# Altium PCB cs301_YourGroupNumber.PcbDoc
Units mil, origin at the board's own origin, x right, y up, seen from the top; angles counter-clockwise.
Board outline 10825 x 6635 mil, 2 copper layers (Top Layer, Bottom Layer); 13 components, 95 nets, 86 pads, 0 vias.
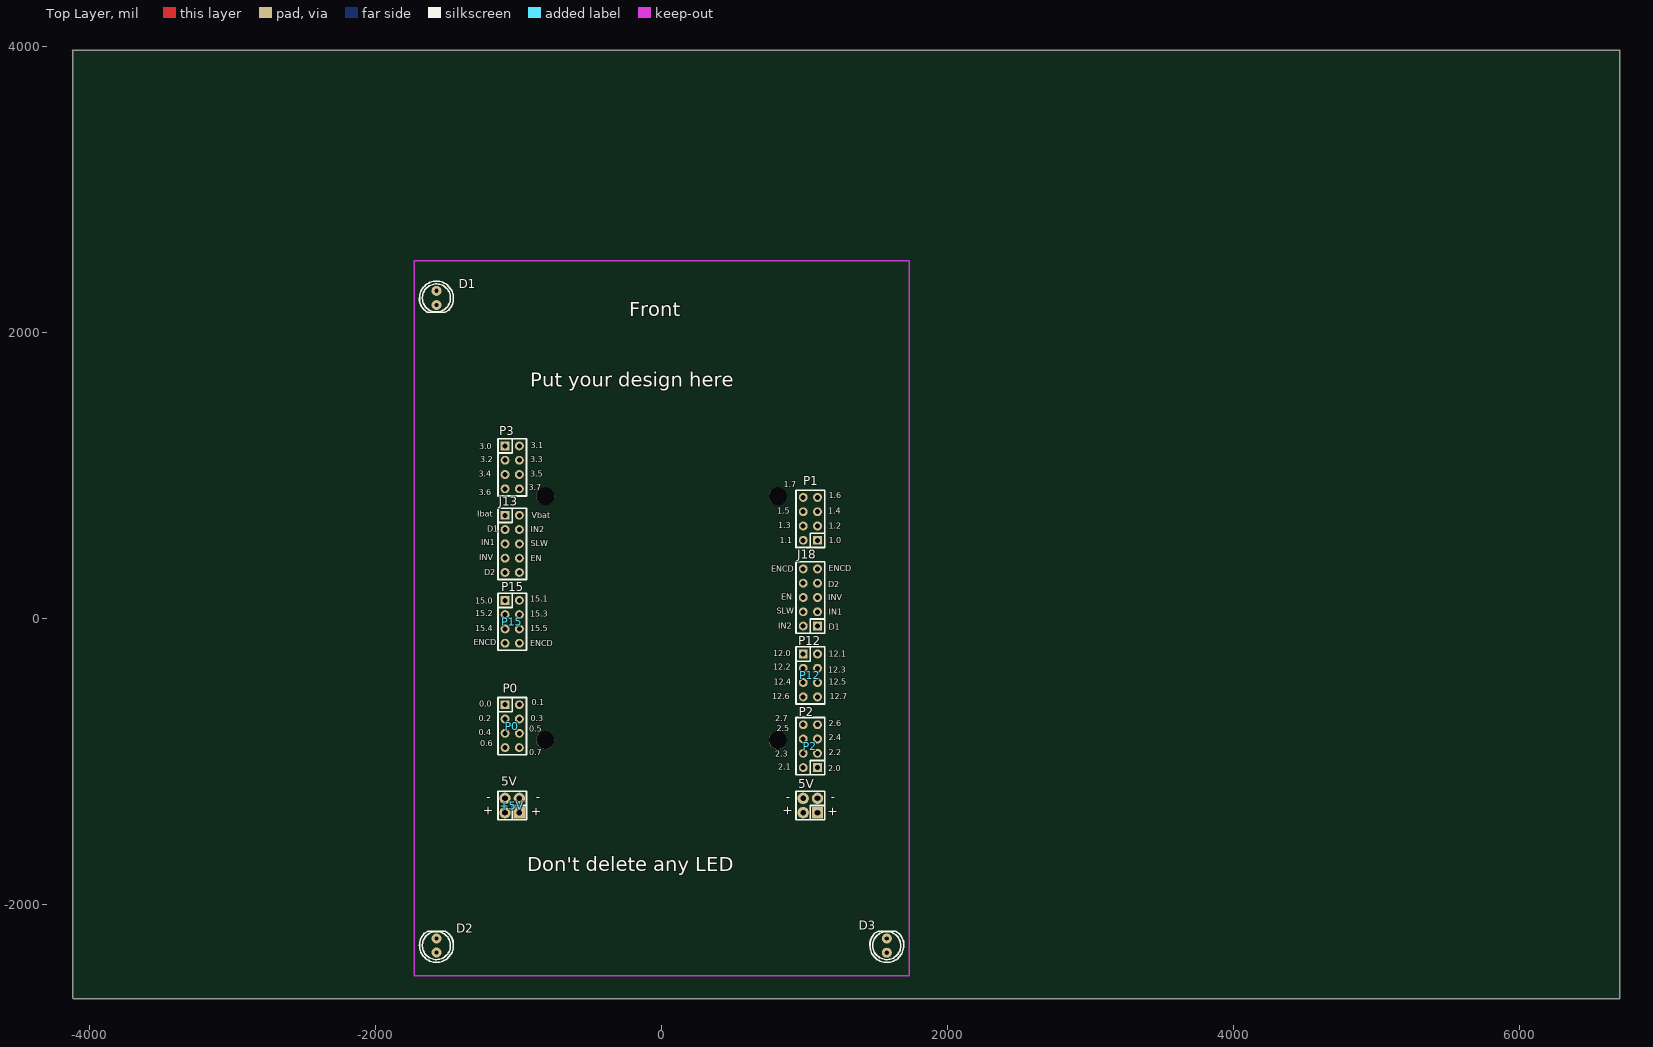
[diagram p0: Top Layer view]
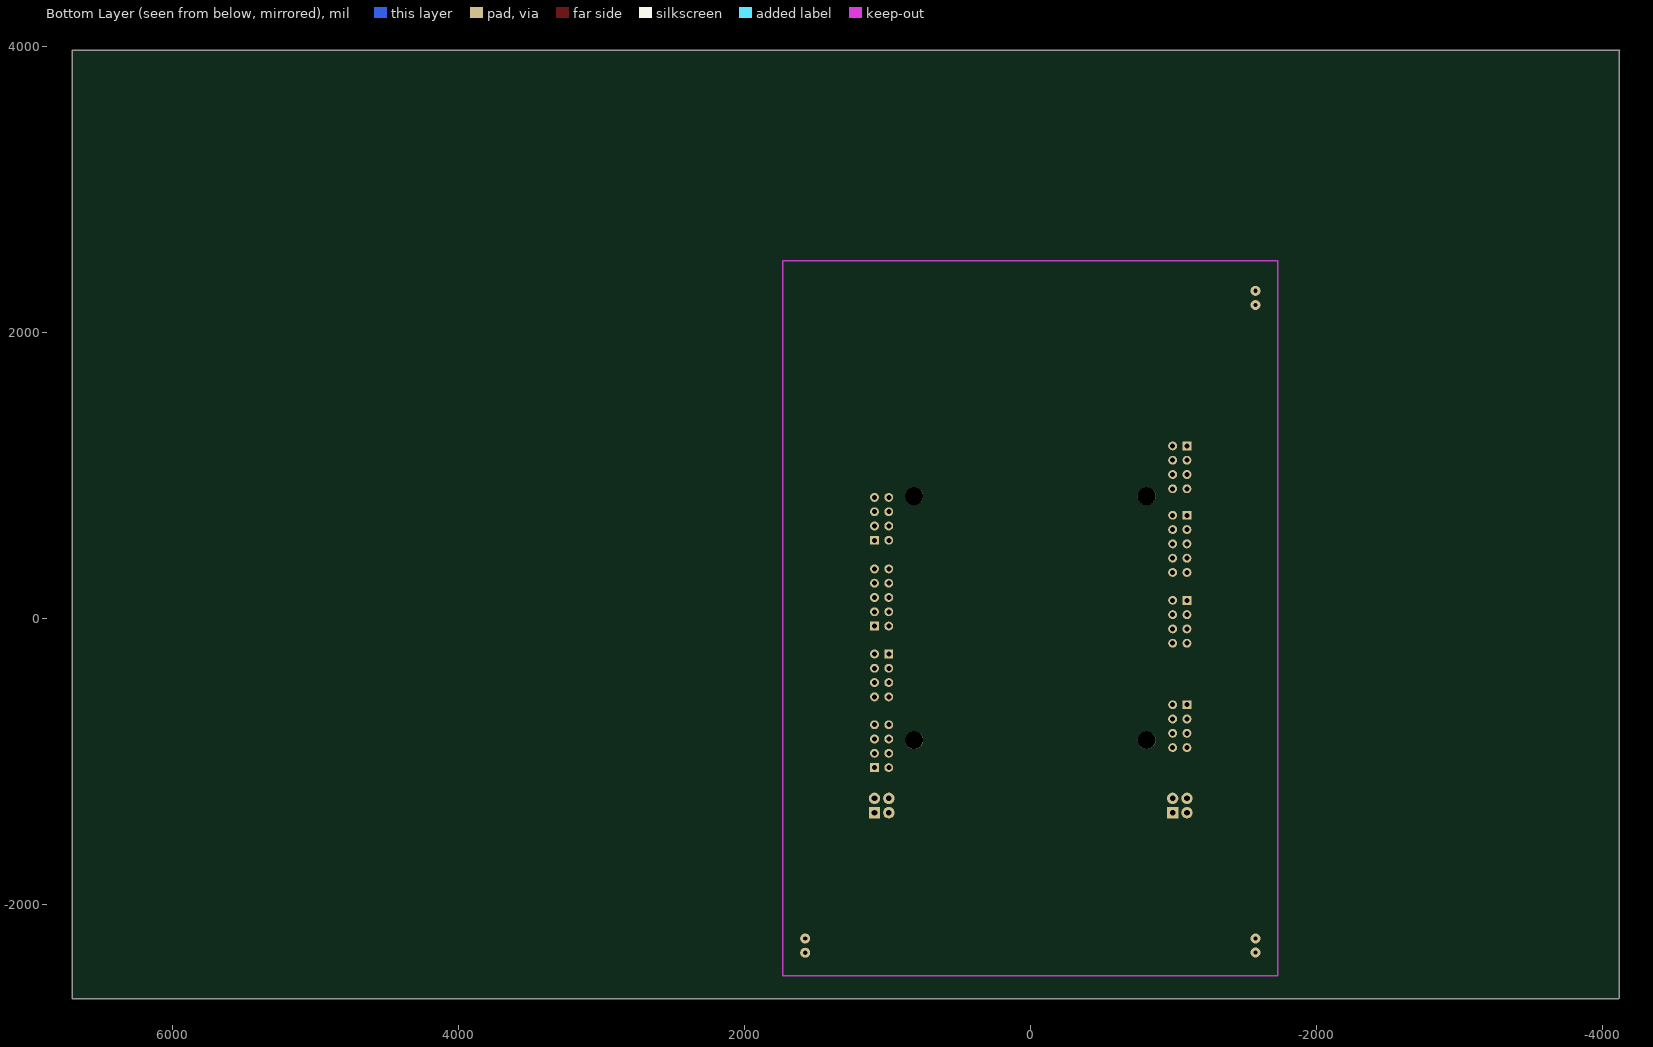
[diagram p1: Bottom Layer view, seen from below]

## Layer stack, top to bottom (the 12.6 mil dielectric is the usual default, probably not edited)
Top Solder: solder mask 0.4, Solder Resist, Dk 3.5
Top Layer: signal copper 1.4
Dielectric1: dielectric 12.6, FR-4, Dk 4.8
Bottom Layer: signal copper 1.4
Bottom Solder: solder mask 0.4, Solder Resist, Dk 3.5

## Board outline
-4118.11,-2656.69 -4113.11,-2661.69 6701.89,-2661.69 6701.89,3973.31 -4123.11,3973.31 -4118.11,3968.31 -4118.11,-2656.69

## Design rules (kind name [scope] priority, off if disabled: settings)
Clearance [All] p1: gap=10
PolygonConnect [All] p1: connectstyle=Relief reliefconductorwidth=20 reliefentries=4 polygonreliefangle="90 Angle" airgapwidth=10
RoutingVias [All] p1: holewidth=28 width=50 viastyle="Through Hole" minholewidth=28 minwidth=50 maxholewidth=28 maxwidth=50
SilkToSolderMaskClearance SilkscreenOverComponentPads [IsPad] p1: minsilkscreentomaskgap=10 clearancetoexposedcopper=TRUE
SolderMaskExpansion [All] p1: expansion=4
UnpouredPolygon [All] p1: allowunpoured=FALSE
Width [All] p1: maxlimit=30 minlimit=10 preferedwidth=10 minimp=50.000000 maximp=50.000000 favimp=50.000000
28 further rules are at their usual default settings.

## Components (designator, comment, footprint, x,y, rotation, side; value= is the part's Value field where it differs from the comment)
5V "5V" IDC4 1090,-1360 r90 top locked
+5V "5V" IDC4 -995,-1360 r90 top locked
D1 "LED_S" LED0.1/5MM#1 -1574.8,2189.76 r180 top locked
D2 "LED_S" LED0.1/5MM#2 -1574.8,-2239.37 r0 top locked (schematic designator D4)
D3 "LED_S" LED0.1/5MM#1 1574.8,-2239.37 r0 top locked
J13 "CON10" IDC10 -1095,720 r270 top locked
J18 "CON10" IDC10 1090,-55 r90 top locked
P0 "P0" idc8 -1095,-605 r270 top locked
P1 "P1" idc8 1090,545 r90 top locked
P2 "P2" idc8 1090,-1045 r90 top locked
P3 "P3" idc8 -1095,1205 r270 top locked
P12 "P12" idc8 990,-250 r270 top locked
P15 "P15" IDC8 -1095,125 r270 top locked

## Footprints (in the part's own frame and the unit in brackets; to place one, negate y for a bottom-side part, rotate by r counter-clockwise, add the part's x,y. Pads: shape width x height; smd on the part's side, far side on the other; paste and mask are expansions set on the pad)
IDC4 [mil]
  rect 80x80 hole 40: 1(0,0)
  round 80 hole 40: 2(0,100) 3(100,0) 4(100,100)
  silkscreen extent -50,-50 150,150
idc8 [mil]
  rect 62x62 hole 35: 1(0,0)
  round 62 hole 35: 2(0,100) 3(100,0) 4(100,100) 5(200,0) 6(200,100) 7(300,0) 8(300,100)
  silkscreen extent -50,-50 350,150
IDC8 [mil]
  rect 62x62 hole 35: 1(0,0)
  round 62 hole 35: 2(0,100) 3(100,0) 4(100,100) 5(200,0) 6(200,100) 7(300,0) 8(300,100)
  silkscreen extent -50,-50 350,150
IDC10 [mil]
  rect 62x62 hole 35: 1(0,0)
  round 62 hole 35: 2(0,100) 3(100,0) 4(100,100) 5(200,0) 6(200,100) 7(300,0) 8(300,100) 9(400,0) 10(400,100)
  silkscreen extent -50,-50 450,150
LED0.1/5MM#1 [mil]
  round 70 hole 30: A(0,0) K(0,-100)
  silkscreen extent -118,-168 118,50
LED0.1/5MM#2 [mil]
  round 70 hole 30: A(0,0) K(0,-98.43)
  silkscreen extent -118,-168 118,50

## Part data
5V +5V: library part CON4, "Connector"
J13 J18: "Connector"
P0 P1 P2 P3: library part CON8, "Connector"
P12 P15: library part CON8_1, "Connector"

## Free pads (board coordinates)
  round 125.98 hole 125.98 unplated: 1(-813,-853) 1(-813,853) 1(813,-853) 1(813,853)

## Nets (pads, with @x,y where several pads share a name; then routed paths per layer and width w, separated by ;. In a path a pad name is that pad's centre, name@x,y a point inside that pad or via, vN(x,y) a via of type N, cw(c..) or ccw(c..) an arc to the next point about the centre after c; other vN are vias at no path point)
5V: 
GND: 
NetC2_1: 
NetC2_2: 
NetC3_1: 
NetC5_1: 
NetC5_2: 
NetC6_1: 
NetC8_1: 
NetC8_2: 
NetC9_1: 
NetC11_1: 
NetC11_2: 
NetC12_1: 
NetC14_1: 
NetC14_2: 
NetC15_1: 
NetC17_1: 
NetC17_2: 
NetC18_1: 
NetC20_1: 
NetC20_2: 
NetC21_1: 
NetC23_1: 
NetC23_2: 
NetC24_1: 
NetC26_1: 
NetC26_2: 
NetC27_1: 
NetC29_1: 
NetC29_2: 
NetC30_1: 
NetC32_1: 
NetC32_2: 
NetC33_1: 
NetC35_1: 
NetC35_2: 
NetC36_1: 
NetD1_A: 
NetD2_A: 
NetD3_A: 
NetD4_A: 
NetJ3_1: 
NetJ3_2: 
NetJ3_12: 
NetJ3_13: 
NetJ3_14: 
NetR2_2: 
NetR4_1: 
NetR5_2: 
NetR9_2: 
NetR11_1: 
NetR12_2: 
NetR16_2: 
NetR18_1: 
NetR19_2: 
NetR23_2: 
NetR25_1: 
NetR26_2: 
NetR30_2: 
NetR32_1: 
NetR33_2: 
NetR37_2: 
NetR39_1: 
NetR40_2: 
NetR44_2: 
NetR46_1: 
NetR47_2: 
NetR51_2: 
NetR53_1: 
NetR54_2: 
NetR58_2: 
NetR60_1: 
NetR61_2: 
NetR65_2: 
NetR67_1: 
NetR68_2: 
NetR72_2: 
NetR74_1: 
NetR75_2: 
NetR79_2: 
NetR81_1: 
NetR82_2: 
O1: 
O2: 
O3: 
O4: 
O5: 
O6: 
O7: 
O8: 
O9: 
O10: 
O11: 
O12: 
pads on no net: 5V.1 5V.2 5V.3 5V.4 +5V.1 +5V.2 +5V.3 +5V.4 D1.A D1.K D2.A D2.K D3.A D3.K J13.1 J13.2 J13.3 J13.4 J13.5 J13.6 J13.7 J13.8 J13.9 J13.10 J18.1 J18.2 J18.3 J18.4 J18.5 J18.6 J18.7 J18.8 J18.9 J18.10 P0.1 P0.2 P0.3 P0.4 P0.5 P0.6 P0.7 P0.8 P1.1 P1.2 P1.3 P1.4 P1.5 P1.6 P1.7 P1.8 P2.1 P2.2 P2.3 P2.4 P2.5 P2.6 P2.7 P2.8 P3.1 P3.2 P3.3 P3.4 P3.5 P3.6 P3.7 P3.8 P12.1 P12.2 P12.3 P12.4 P12.5 P12.6 P12.7 P12.8 P15.1 P15.2 P15.3 P15.4 P15.5 P15.6 P15.7 P15.8

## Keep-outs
Keep-Out Layer:
  lines w10: -1730,-2500 -1730,2500 1730,2500 1730,-2500 -1730,-2500

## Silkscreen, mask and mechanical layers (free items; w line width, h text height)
Top Overlay:
  text "Front" at -228.11,2113.31 h100
  text "Put your design here" at -920,1620 h100
  text "3.1" at -915,1190 h40
  text "3.0" at -1275,1180 h40
  text "3.2" at -1270,1090 h40
  text "3.3" at -920,1090 h40
  text "3.4" at -1280,990 h40
  text "3.5" at -920,990 h40
  text "1.7" at 855,915 h40
  text "3.7" at -930,895 h40
  text "3.6" at -1280,860 h40
  text "1.6" at 1170,840 h40
  text "1.5" at 810,730 h40
  text "1.4" at 1165,730 h40
  text "Ibat" at -1290,710 h40
  text "Vbat" at -910,700 h40
  text "1.3" at 815,630 h40
  text "1.2" at 1170,625 h40
  text "D1" at -1220,605 h40
  text "IN2" at -915,600 h40
  text "1.1" at 825,525 h40
  text "1.0" at 1170,525 h40
  text "IN1" at -1260,510 h40
  text "SLW" at -915,505 h40
  text "INV" at -1275,405 h40
  text "EN" at -915,400 h40
  text "ENCD" at 1170,330 h40
  text "ENCD" at 765,325 h40
  text "D2" at -1240,300 h40
  text "D2" at 1165,215 h40
  text "EN" at 835,130 h40
  text "INV" at 1165,125 h40
  text "15.1" at -920,115 h40
  text "15.0" at -1305,100 h40
  text "SLW" at 805,30 h40
  text "IN1" at 1170,25 h40
  text "15.2" at -1305,15 h40
  text "15.3" at -920,10 h40
  text "IN2" at 815,-75 h40
  text "D1" at 1170,-80 h40
  text "15.4" at -1305,-90 h40
  text "15.5" at -920,-90 h40
  text "ENCD" at -1315,-190 h40
  text "ENCD" at -920,-195 h40
  text "12.0" at 780,-265 h40
  text "12.1" at 1170,-270 h40
  text "12.2" at 780,-360 h40
  text "12.3" at 1165,-380 h40
  text "12.4" at 785,-465 h40
  text "12.5" at 1170,-465 h40
  text "12.6" at 775,-565 h40
  text "12.7" at 1175,-565 h40
  text "0.1" at -910,-610 h40
  text "0.0" at -1275,-620 h40
  text "0.2" at -1280,-720 h40
  text "0.3" at -915,-720 h40
  text "2.7" at 795,-720 h40
  text "2.6" at 1170,-755 h40
  text "2.5" at 805,-790 h40
  text "0.5" at -925,-795 h40
  text "0.4" at -1280,-820 h40
  text "2.4" at 1170,-855 h40
  text "0.6" at -1270,-895 h40
  text "0.7" at -925,-960 h40
  text "2.2" at 1170,-960 h40
  text "2.3" at 795,-970 h40
  text "2.1" at 815,-1060 h40
  text "2.0" at 1165,-1070 h40
  text "-" at -1195,-1230 h60 r180
  text "-" at -850,-1230 h60 r180
  text "-" at 900,-1230 h60 r180
  text "-" at 1215,-1230 h60 r180
  text "+" at -1185,-1380 h60 r90
  text "+" at 910,-1380 h60 r90
  text "+" at -850,-1390 h60 r90
  text "+" at 1225,-1390 h60 r90
  text "Don't delete any LED" at -940,-1770 h100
